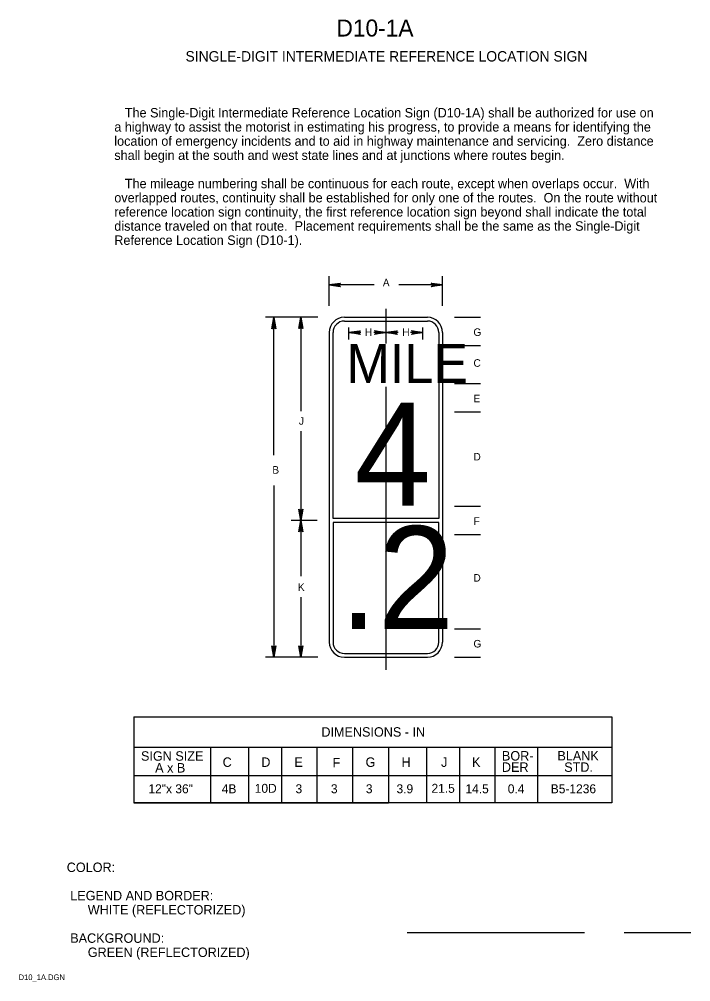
# Model space of a CAD drawing. Extents: x 0.013 to 0.191, y 0.004 to 0.259.
import ezdxf

# ---------------------------------------------------------------- set-up
doc = ezdxf.new("R2010")
doc.units = 0
doc.layers.add('1', color=7, linetype='Continuous')
doc.layers.add('3', color=7, linetype='Continuous')

# ---------------------------------------------------------------- blocks, each defined once
blk = doc.blocks.new('RARROW')
at = {"layer": '3'}
for p, q in [((-2.156, 0.285), (-2.2665, 0.384625)), ((-2.2665, 0.384625), (0, 0)), ((0, 0), (-2.2665, -0.379125)), ((-2.156, 0.285), (-2.075625, 0.12075)), ((0, 0), (-2.156, 0.285)), ((-2.14975, -0.2705), (0, 0)), ((-2.075625, 0.12075), (0, 0)), ((0, 0), (-2.074, -0.108)), ((-2.2665, -0.379125), (-2.14975, -0.2705)), ((-2.074, -0.108), (-2.14975, -0.2705))]:
    blk.add_line(p, q, dxfattribs=at)

msp = doc.modelspace()

# ---------------------------------------------------------------- linework, layer by layer
at = {"layer": '1'}
for p, q in [((0.11544, 0.01695), (0.16242, 0.01695)), ((0.17295, 0.01695), (0.19056, 0.01695))]:
    msp.add_line(p, q, dxfattribs=at)
at = {"layer": '3'}
for p, q in [((0.0948, 0.18291), (0.0948, 0.19081)), ((0.1248, 0.18291), (0.1248, 0.19081)), ((0.10669, 0.18845), (0.0948, 0.18845)), ((0.1248, 0.18845), (0.11325, 0.18845)), ((0.1098, 0.18209), (0.1098, 0.17292)), ((0.09177, 0.17988), (0.07794, 0.17988)), ((0.08011, 0.1434), (0.08011, 0.17988)), ((0.08727, 0.17988), (0.08727, 0.15507)), ((0.0988, 0.17988), (0.1208, 0.17988)), ((0.0988, 0.17888), (0.1208, 0.17888)), ((0.12799, 0.17988), (0.13486, 0.17988)), ((0.0948, 0.17588), (0.0948, 0.09388)), ((0.0958, 0.12658), (0.0958, 0.17588)), ((0.1, 0.17397), (0.1, 0.17722)), ((0.1196, 0.17397), (0.1196, 0.17722)), ((0.1238, 0.17588), (0.1238, 0.12658)), ((0.1248, 0.17588), (0.1248, 0.09388)), ((0.10318, 0.17585), (0.1, 0.17585)), ((0.11304, 0.17585), (0.10662, 0.17585)), ((0.1196, 0.17585), (0.11633, 0.17585)), ((0.12799, 0.17238), (0.13486, 0.17238)), ((0.1098, 0.16147), (0.1098, 0.08652)), ((0.12799, 0.16238), (0.13486, 0.16238)), ((0.12799, 0.15488), (0.13486, 0.15488)), ((0.08727, 0.14972), (0.08727, 0.12608)), ((0.08011, 0.13533), (0.08011, 0.08988)), ((0.12799, 0.12988), (0.13486, 0.12988)), ((0.09161, 0.12608), (0.08473, 0.12608)), ((0.08727, 0.12608), (0.08727, 0.11134)), ((0.1238, 0.12658), (0.0958, 0.12658)), ((0.1238, 0.12558), (0.0958, 0.12558)), ((0.0958, 0.12558), (0.0958, 0.09388)), ((0.1238, 0.09388), (0.1238, 0.12558)), ((0.12799, 0.12238), (0.13486, 0.12238)), ((0.08727, 0.10581), (0.08727, 0.08988)), ((0.12799, 0.09738), (0.13486, 0.09738)), ((0.09177, 0.08988), (0.07794, 0.08988)), ((0.0988, 0.09088), (0.1208, 0.09088)), ((0.0988, 0.08988), (0.1208, 0.08988)), ((0.12799, 0.08988), (0.13486, 0.08988)), ((0.04303, 0.07412), (0.16967, 0.07412)), ((0.04303, 0.07412), (0.04303, 0.0513)), ((0.16967, 0.07412), (0.16967, 0.0513)), ((0.16967, 0.066), (0.04303, 0.066)), ((0.06332, 0.06585), (0.06332, 0.0513)), ((0.07343, 0.066), (0.07343, 0.0513)), ((0.08212, 0.06585), (0.08212, 0.0513)), ((0.09152, 0.06585), (0.09152, 0.0513)), ((0.10092, 0.06585), (0.10092, 0.0513)), ((0.11049, 0.066), (0.11049, 0.0513)), ((0.1206, 0.066), (0.1206, 0.0513)), ((0.12929, 0.06585), (0.12929, 0.0513)), ((0.13869, 0.06585), (0.13869, 0.0513)), ((0.14997, 0.06585), (0.14997, 0.0513)), ((0.04303, 0.05859), (0.16967, 0.05859)), ((0.16967, 0.0513), (0.04303, 0.0513)), ((0.04303, 0.0513), (0.11049, 0.0513)), ((0.11049, 0.0513), (0.04326, 0.0513))]:
    msp.add_line(p, q, dxfattribs=at)
for centre, radius, start, end in [((0.0988, 0.17588), 0.004, 90, 180), ((0.0988, 0.17588), 0.003, 90, 180), ((0.1208, 0.17588), 0.004, 0, 90), ((0.1208, 0.17588), 0.003, 0, 90), ((0.0988, 0.09388), 0.004, 180, 270), ((0.0988, 0.09388), 0.003, 180, 270), ((0.1208, 0.09388), 0.003, 270, 0), ((0.1208, 0.09388), 0.004, 270, 0)]:
    msp.add_arc(centre, radius, start, end, dxfattribs=at)

# ---------------------------------------------------------------- block references
at = {"layer": '3', "xscale": 0.0013236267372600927, "yscale": 0.001309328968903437}
for p, rotation in [((0.0948, 0.18845), 180), ((0.08011, 0.1798), 90), ((0.08727, 0.17988), 90), ((0.1, 0.17585), 180), ((0.1098, 0.17585), 180), ((0.08727, 0.12608), -90), ((0.08727, 0.12608), 90), ((0.08011, 0.08988), -90), ((0.08727, 0.08988), -90)]:
    msp.add_blockref('RARROW', p, dxfattribs=dict(at, rotation=rotation))
for p in [(0.1248, 0.18845), (0.1098, 0.17585), (0.1196, 0.17585)]:
    msp.add_blockref('RARROW', p, dxfattribs=at)

# ---------------------------------------------------------------- texts
at = {"layer": '1'}
for s, height, p in [('D10-1A', 0.0045, (0.09671, 0.25424)), ('SINGLE-DIGIT INTERMEDIATE REFERENCE LOCATION SIGN', 0.0027503, (0.05671, 0.24762)), ('COLOR:', 0.0025, (0.02525, 0.033)), (' LEGEND AND BORDER:', 0.0024998, (0.02525, 0.0255)), ('      WHITE (REFLECTORIZED)', 0.0024998, (0.02525, 0.02175)), (' BACKGROUND:', 0.0024998, (0.02525, 0.01425)), ('      GREEN (REFLECTORIZED)', 0.0024998, (0.02525, 0.0105)), ('D10_1A.DGN', 0.0015, (0.0125, 0.00438))]:
    msp.add_text(s, height=height, dxfattribs=at).set_placement(p)
at = {"layer": '3'}
for s, height, p in [('   The Single-Digit Intermediate Reference Location Sign (D10-1A) shall be authorized for use on', 0.0024998, (0.03785, 0.23281)), ('a highway to assist the motorist in estimating his progress, to provide a means for identifying the', 0.0024998, (0.03785, 0.22906)), ('location of emergency incidents and to aid in highway maintenance and servicing.  Zero distance', 0.0024998, (0.03785, 0.22531)), ('shall begin at the south and west state lines and at junctions where routes begin.', 0.0024998, (0.03785, 0.22156)), ('   The mileage numbering shall be continuous for each route, except when overlaps occur.  With', 0.0024998, (0.03785, 0.21406)), ('overlapped routes, continuity shall be established for only one of the routes.  On the route without', 0.0024998, (0.03785, 0.21031)), ('reference location sign continuity, the first reference location sign beyond shall indicate the total ', 0.00249975, (0.03785, 0.20656)), ('distance traveled on that route.  Placement requirements shall be the same as the Single-Digit ', 0.0024998, (0.03785, 0.20281)), ('Reference Location Sign (D10-1).', 0.0024998, (0.03785, 0.19906)), ('A', 0.002, (0.10899, 0.18808)), ('H', 0.002, (0.10423, 0.17495)), ('H', 0.002, (0.11415, 0.17495)), ('G', 0.002, (0.133, 0.17495)), ('MILE', 0.010321, (0.09934, 0.16251)), ('C', 0.002, (0.133, 0.16679)), ('E', 0.002, (0.13301, 0.15738)), ('4', 0.02726, (0.10149, 0.13004)), ('J', 0.002, (0.08675, 0.15144)), ('D', 0.002, (0.133, 0.14197)), ('B', 0.002, (0.07973, 0.13848)), ('.2', 0.027261, (0.0975, 0.09733)), ('F', 0.002, (0.13305, 0.12492)), ('D', 0.002, (0.133, 0.1099)), ('K', 0.002, (0.08648, 0.10744)), ('G', 0.002, (0.133, 0.09246)), ('DIMENSIONS - IN', 0.0024998, (0.09271, 0.06884)), ('SIGN SIZE', 0.0025, (0.04492, 0.06247)), ('BOR-', 0.0025, (0.14054, 0.06252)), ('BLANK', 0.0025, (0.15524, 0.06253)), ('A x B', 0.0025, (0.04867, 0.05934)), ('C', 0.0025, (0.06655, 0.06084)), ('D', 0.0025, (0.0768, 0.06084)), ('E', 0.0025, (0.08555, 0.06084)), ('F', 0.0025, (0.09567, 0.06072)), ('G', 0.0025, (0.10442, 0.06084)), ('H', 0.0025, (0.11395, 0.06084)), ('J', 0.0025, (0.12442, 0.06084)), ('K', 0.0025, (0.13261, 0.06084)), ('DER', 0.0025, (0.14054, 0.05952)), ('STD.', 0.0025, (0.15704, 0.05953)), ('12"x 36"', 0.002375, (0.04689, 0.05385)), ('4B', 0.002375, (0.06631, 0.05385)), ('10D', 0.002375, (0.07505, 0.05397)), ('3', 0.00238, (0.08585, 0.05385)), ('3', 0.00238, (0.09523, 0.05385)), ('3', 0.00238, (0.10448, 0.05385)), ('3.9', 0.002375, (0.11261, 0.05385)), ('21.5', 0.002375, (0.12187, 0.05397)), ('14.5', 0.002375, (0.13087, 0.05385)), ('0.4', 0.002375, (0.14209, 0.05385)), ('B5-1236', 0.002375, (0.15347, 0.05385))]:
    msp.add_text(s, height=height, dxfattribs=at).set_placement(p)

doc.saveas('drawing.dxf')
